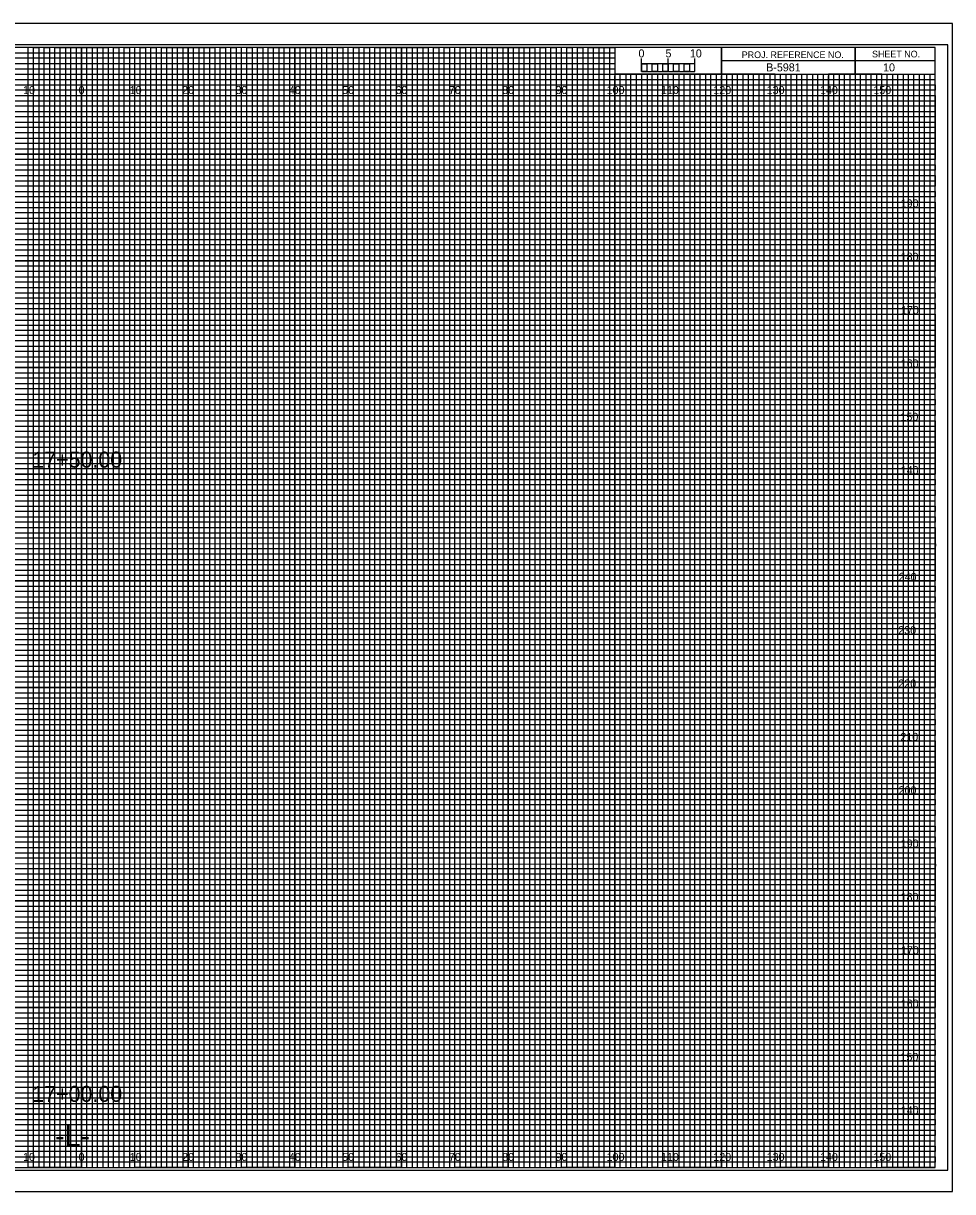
# Model space of a CAD drawing. Extents: x -13 to 323, y -5 to 4174.
# Drawn here: x 149.1 to 323.3, y 875.5 to 1094.5 of the extents above; entities that cross this region are included whole.
import ezdxf

# ---------------------------------------------------------------- set-up
doc = ezdxf.new("R2010")
doc.units = 0
for name, color, linetype in [('Exist Cross Section Cell', 7, 'Continuous'), ('Exist XS Center Line Elevation Label', 7, 'Continuous'), ('Exist XS Ground Line', 7, 'Continuous'), ('Prop CMT Concrete Structures', 7, 'Continuous'), ('Prop CMT Guardrail Graphics', 7, 'Continuous'), ('Prop CMT Pvmt Course 1', 7, 'Continuous'), ('Prop CMT Pvmt Course 2', 7, 'Continuous'), ('Prop CMT Pvmt Course 3', 7, 'Continuous'), ('Prop CMT Pvmt Surface', 7, 'Continuous'), ('Prop CMT Shld Paved Course 1', 7, 'Continuous'), ('Prop CMT Shld Paved Course 2', 7, 'Continuous'), ('Prop CMT Shld Paved Course 3', 7, 'Continuous'), ('Prop CMT Subgrade Earthwork', 7, 'Continuous'), ('Prop XS Ditch Standard Text', 7, 'Continuous'), ('Prop XS SE Text', 7, 'Continuous'), ('Prop XS Side Slope Text', 7, 'Continuous'), ('Scratch_Level_0', 7, 'Continuous')]:
    doc.layers.add(name, color=color, linetype=linetype)

msp = doc.modelspace()

# ---------------------------------------------------------------- linework, layer by layer
at = {"layer": 'Exist XS Center Line Elevation Label'}
for points in [[(145, 880), (155, 880), (155, 1090), (165, 1090), (165, 880), (175, 880), (175, 1090), (185, 1090), (185, 880), (195, 880), (195, 1090), (205, 1090), (205, 880), (215, 880), (215, 1090), (225, 1090), (225, 880), (235, 880), (235, 1090), (245, 1090), (245, 880), (255, 880), (255, 1090), (259.93, 1090), (260, 1090), (260, 1085), (264.99, 1085), (264.99, 880), (275, 880), (275, 1085), (285, 1085), (285, 880), (295, 880), (295, 1085), (305, 1085), (305, 880), (315, 880), (315, 1085)], [(0, 1085), (275, 1085)], [(0, 1065), (320, 1065), (320, 1075), (0, 1075)], [(0, 1045), (320, 1045), (320, 1055), (0, 1055)], [(0, 1025), (320, 1025), (320, 1035), (0, 1035)], [(0, 1005), (320, 1005), (320, 1015), (0, 1015)], [(0, 985), (320, 985), (320, 995), (0, 995)], [(0, 965), (320, 965), (320, 975), (0, 975)], [(0, 945), (320, 945), (320, 955), (0, 955)], [(0, 925), (320, 925), (320, 935), (0, 935)], [(0, 905), (320, 905), (320, 915), (0, 915)], [(0, 885), (320, 885), (320, 895), (0, 895)]]:
    msp.add_lwpolyline(points, dxfattribs=at)
at = {"layer": 'Exist XS Ground Line'}
for p, q in [((150, 1090), (140, 1090)), ((150, 880), (150, 1090)), ((170, 1090), (160, 1090)), ((160, 1090), (160, 880)), ((170, 880), (170, 1090)), ((190, 1090), (180, 1090)), ((180, 1090), (180, 880)), ((190, 880), (190, 1090)), ((210, 1090), (200, 1090)), ((200, 1090), (200, 880)), ((210, 880), (210, 1090)), ((230, 1090), (220, 1090)), ((220, 1090), (220, 880)), ((230, 880), (230, 1090)), ((250, 1090), (240, 1090)), ((240, 1090), (240, 880)), ((250, 880), (250, 1090)), ((260, 1090), (260, 880)), ((270, 880), (270, 1085)), ((290, 1085), (280, 1085)), ((280, 1085), (280, 880)), ((290, 880), (290, 1085)), ((310, 1085), (300, 1085)), ((300, 1085), (300, 880)), ((310, 880), (310, 1085)), ((160, 880), (150, 880)), ((180, 880), (170, 880)), ((200, 880), (190, 880)), ((220, 880), (210, 880)), ((240, 880), (230, 880)), ((260, 880), (250, 880)), ((280, 880), (270, 880)), ((300, 880), (290, 880)), ((320, 880), (310, 880)), ((320, 880), (320, 880))]:
    msp.add_line(p, q, dxfattribs=at)
for points in [[(0, 1080), (320, 1080), (320, 1070), (0, 1070)], [(0, 1060), (320, 1060), (320, 1050), (0, 1050)], [(0, 1040), (320, 1040), (320, 1030), (0, 1030)], [(0, 1020), (320, 1020), (320, 1010), (0, 1010)], [(0, 1000), (320, 1000), (320, 990), (0, 990)], [(0, 980), (320, 980), (320, 970), (0, 970)], [(0, 960), (320, 960), (320, 950), (0, 950)], [(0, 940), (320, 940), (320, 930), (0, 930)], [(0, 920), (320, 920), (320, 910), (0, 910)], [(0, 900), (320, 900), (320, 890), (0, 890)]]:
    msp.add_lwpolyline(points, dxfattribs=at)
at = {"layer": 'Prop CMT Pvmt Course 1'}
for p, q in [((323.3, 1094.5), (-13.4, 1094.5)), ((-13.4, 875.5), (323.3, 875.5))]:
    msp.add_line(p, q, dxfattribs=at)
at = {"layer": 'Prop CMT Pvmt Course 2'}
msp.add_lwpolyline([(-13.4, 875.5), (323.3, 875.5), (323.3, 1094.5), (-13.4, 1094.5)], close=True, dxfattribs=at)
at = {"layer": 'Prop CMT Pvmt Course 3'}
msp.add_lwpolyline([(-10.8, 879.5), (322.4, 879.5), (322.4, 1090.5), (-10.8, 1090.5)], close=True, dxfattribs=at)
at = {"layer": 'Prop CMT Shld Paved Course 1'}
for p, q in [((305, 1090), (305, 1085)), ((305, 1085), (305, 1090)), ((280, 1087.5), (280, 1085)), ((320, 1087.49), (280, 1087.49)), ((280, 1085), (320, 1085))]:
    msp.add_line(p, q, dxfattribs=at)
for points in [[(320, 1090), (0, 1090), (0, 880), (320, 880)], [(280, 1090), (260, 1090), (260, 1085.03), (280, 1085.03)], [(320, 1090), (280, 1090), (280, 1085), (320, 1085)]]:
    msp.add_lwpolyline(points, close=True, dxfattribs=at)
at = {"layer": 'Prop CMT Shld Paved Course 2'}
for p, q in [((267, 1085), (266.01, 1085)), ((266.01, 1085), (266.01, 880)), ((267, 880), (267, 1085)), ((269, 1085), (268, 1085)), ((268, 1085), (268, 880)), ((269, 880), (269, 1085)), ((266.01, 880), (265, 880)), ((268, 880), (267, 880))]:
    msp.add_line(p, q, dxfattribs=at)
for points in [[(150, 880), (151, 880), (151, 1090), (152, 1090), (152, 880)], [(152, 880), (153, 880), (153, 1090), (154, 1090), (154, 880)], [(155, 880), (156, 880), (156, 1090), (157, 1090), (157, 880)], [(157, 880), (158, 880), (158, 1090), (159, 1090), (159, 880)], [(160, 880), (161, 880), (161, 1090), (162, 1090), (162, 880)], [(162, 880), (163, 880), (163, 1090), (164, 1090), (164, 880)], [(165, 880), (166, 880), (166, 1090), (167, 1090), (167, 880)], [(167, 880), (168, 880), (168, 1090), (169, 1090), (169, 880)], [(170, 880), (171, 880), (171, 1090), (172, 1090), (172, 880)], [(172, 880), (173, 880), (173, 1090), (174, 1090), (174, 880)], [(175, 880), (176, 880), (176, 1090), (177, 1090), (177, 880)], [(177, 880), (178, 880), (178, 1090), (179, 1090), (179, 880)], [(180, 880), (181, 880), (181, 1090), (182, 1090), (182, 880)], [(182, 880), (183, 880), (183, 1090), (184, 1090), (184, 880)], [(185, 880), (186, 880), (186, 1090), (187, 1090), (187, 880)], [(187, 880), (188, 880), (188, 1090), (189, 1090), (189, 880)], [(190, 880), (191, 880), (191, 1090), (192, 1090), (192, 880)], [(192, 880), (193, 880), (193, 1090), (194, 1090), (194, 880)], [(195, 880), (196, 880), (196, 1090), (197, 1090), (197, 880)], [(197, 880), (198, 880), (198, 1090), (199, 1090), (199, 880)], [(200, 880), (201, 880), (201, 1090), (202, 1090), (202, 880)], [(202, 880), (203, 880), (203, 1090), (204, 1090), (204, 880)], [(205, 880), (206, 880), (206, 1090), (207, 1090), (207, 880)], [(207, 880), (208, 880), (208, 1090), (209, 1090), (209, 880)], [(210, 880), (211, 880), (211, 1090), (212, 1090), (212, 880)], [(212, 880), (213, 880), (213, 1090), (214, 1090), (214, 880)], [(215, 880), (216, 880), (216, 1090), (217, 1090), (217, 880)], [(217, 880), (218, 880), (218, 1090), (219, 1090), (219, 880)], [(220, 880), (221, 880), (221, 1090), (222, 1090), (222, 880)], [(222, 880), (223, 880), (223, 1090), (224, 1090), (224, 880)], [(225, 880), (226, 880), (226, 1090), (227, 1090), (227, 880)], [(227, 880), (228, 880), (228, 1090), (229, 1090), (229, 880)], [(230, 880), (231, 880), (231, 1090), (232, 1090), (232, 880)], [(232, 880), (233, 880), (233, 1090), (234, 1090), (234, 880)], [(235, 880), (236, 880), (236, 1090), (237, 1090), (237, 880)], [(237, 880), (238, 880), (238, 1090), (239, 1090), (239, 880)], [(240, 880), (241, 880), (241, 1090), (242, 1090), (242, 880)], [(242, 880), (243, 880), (243, 1090), (244, 1090), (244, 880)], [(245, 880), (246, 880), (246, 1090), (247, 1090), (247, 880)], [(247, 880), (248, 880), (248, 1090), (249, 1090), (249, 880)], [(250, 880), (251, 880), (251, 1090), (252, 1090), (252, 880)], [(252, 880), (253, 880), (253, 1090), (254, 1090), (254, 880)], [(255, 880), (256, 880), (256, 1090), (257, 1090), (257, 880)], [(257, 880), (258, 880), (258, 1090), (259, 1090), (259, 880)], [(260, 880), (261, 880), (261, 1085), (262.02, 1085), (262.02, 880)], [(262, 880), (263, 880), (263, 1085), (263.99, 1085), (263.99, 880)], [(270, 880), (270.98, 880), (270.98, 1085), (272, 1085), (272, 880)], [(272, 880), (273, 880), (273, 1085), (274.05, 1085), (274.05, 880)], [(275, 880), (276, 880), (276, 1085), (277, 1085), (277, 880)], [(277, 880), (278, 880), (278, 1085), (279, 1085), (279, 880)], [(280, 880), (281, 880), (281, 1085), (282, 1085), (282, 880)], [(282, 880), (283, 880), (283, 1085), (284, 1085), (284, 880)], [(285, 880), (286, 880), (286, 1085), (287, 1085), (287, 880)], [(287, 880), (288, 880), (288, 1085), (289, 1085), (289, 880)], [(290, 880), (291, 880), (291, 1085), (292, 1085), (292, 880)], [(292, 880), (293, 880), (293, 1085), (294, 1085), (294, 880)], [(295, 880), (296, 880), (296, 1085), (297, 1085), (297, 880)], [(297, 880), (298, 880), (298, 1085), (299, 1085), (299, 880)], [(300, 880), (301, 880), (301, 1085), (302, 1085), (302, 880)], [(302, 880), (303, 880), (303, 1085), (304, 1085), (304, 880)], [(305, 880), (306, 880), (306, 1085), (307, 1085), (307, 880)], [(307, 880), (308, 880), (308, 1085), (309, 1085), (309, 880)], [(310, 880), (311, 880), (311, 1085), (312, 1085), (312, 880)], [(312, 880), (313, 880), (313, 1085), (314, 1085), (314, 880)], [(315, 880), (316, 880), (316, 1085), (317, 1085), (317, 880)], [(317, 880), (318, 880), (318, 1085), (319, 1085), (319, 880)]]:
    msp.add_lwpolyline(points, dxfattribs=at)
at = {"layer": 'Prop CMT Shld Paved Course 3'}
for p, q in [((265, 1085.49), (265, 1087.9)), ((265, 1086.9), (265, 1087.9)), ((270, 1085.49), (270, 1087.9)), ((275, 1085.49), (275, 1087.9)), ((275, 1086.9), (275, 1087.9))]:
    msp.add_line(p, q, dxfattribs=at)
for points in [[(275, 1086.9), (265, 1086.9), (265, 1085.49), (275, 1085.49)], [(265, 1086.9), (266, 1086.9), (266, 1085.49), (265, 1085.49)], [(267, 1086.9), (268, 1086.9), (268, 1085.49), (267, 1085.49)], [(269, 1086.9), (270, 1086.9), (270, 1085.49), (269, 1085.49)], [(271, 1086.9), (272, 1086.9), (272, 1085.49), (271, 1085.49)], [(273, 1086.9), (274, 1086.9), (274, 1085.49), (273, 1085.49)]]:
    msp.add_lwpolyline(points, close=True, dxfattribs=at)
at = {"layer": 'Prop CMT Subgrade Earthwork'}
for p, q in [((150, 880), (150, 1090)), ((160, 880), (160, 1090)), ((170, 880), (170, 1090)), ((180, 880), (180, 1090)), ((190, 880), (190, 1090)), ((200, 880), (200, 1090)), ((210, 880), (210, 1090)), ((220, 880), (220, 1090)), ((230, 880), (230, 1090)), ((240, 880), (240, 1090)), ((250, 880), (250, 1090)), ((260, 880), (260, 1084.69)), ((270, 880), (270, 1084.69)), ((280, 880), (280, 1084.69)), ((290, 880), (290, 1084.69)), ((300, 880), (300, 1084.69)), ((310, 880), (310, 1084.69)), ((0, 1080), (320, 1080)), ((0, 1070), (320, 1070)), ((0, 1060), (320, 1060)), ((0, 1050), (320, 1050)), ((0, 1040), (320, 1040)), ((0, 1030), (320, 1030)), ((0, 1020), (320, 1020)), ((0, 1010), (320, 1010)), ((0, 1000), (320, 1000)), ((0, 990), (320, 990)), ((0, 980), (320, 980)), ((0, 970), (320, 970)), ((0, 960), (320, 960)), ((0, 950), (320, 950)), ((0, 940), (320, 940)), ((0, 930), (320, 930)), ((0, 920), (320, 920)), ((0, 910), (320, 910)), ((0, 900), (320, 900)), ((0, 890), (320, 890))]:
    msp.add_line(p, q, dxfattribs=at)
at = {"layer": 'Scratch_Level_0'}
for p, q in [((0, 1089), (260, 1089)), ((260, 1089), (260, 1087.98)), ((260, 1087.98), (0, 1087.98)), ((0, 1087), (260, 1087)), ((260, 1087), (260, 1085.89)), ((260, 1085.89), (0, 1085.89)), ((0, 1084), (320, 1084))]:
    msp.add_line(p, q, dxfattribs=at)
for points in [[(0, 1083), (270, 1083), (320, 1083), (320, 1082), (0, 1082)], [(0, 1081), (320, 1081), (320, 1079), (0, 1079)], [(0, 1078), (320, 1078), (320, 1077), (0, 1076.98)], [(0, 1076), (320, 1076), (320, 1074), (0, 1074)], [(0, 1073), (320, 1073), (320, 1072), (0, 1072)], [(0, 1071), (320, 1071), (320, 1069), (0, 1069)], [(0, 1068), (320, 1068), (320, 1067), (0, 1067)], [(0, 1066), (320, 1066), (320, 1064), (0, 1064)], [(0, 1063), (320, 1063), (320, 1062), (0, 1062)], [(0, 1061), (320, 1061), (320, 1059), (0, 1059)], [(0, 1058), (320, 1058), (320, 1057), (0, 1057)], [(0, 1056), (320, 1056), (320, 1053.95), (320, 1053), (320, 1052), (0, 1052)], [(0, 1054), (320, 1054), (320, 1053), (0, 1053)], [(0, 1051), (320, 1051), (320, 1049), (0, 1049.03)], [(0, 1049.03), (320, 1049), (320, 1048), (0, 1048)], [(0, 1047), (320, 1047), (320, 1046), (0, 1046)], [(0, 1044), (320, 1044), (320, 1043), (0, 1043)], [(0, 1042), (320, 1042), (320, 1041), (0, 1041)], [(-0.07, 1038.89), (320, 1038.89), (320, 1037.88), (-0.07, 1037.88)], [(0, 1037), (320, 1037), (320, 1036), (0, 1036)], [(0, 1034), (320, 1034), (320, 1033), (0, 1033)], [(0, 1032), (320, 1032), (320, 1031), (0, 1031)], [(0, 1029), (320, 1029), (320, 1028), (0, 1028)], [(0, 1027), (320, 1027), (320, 1026), (0, 1026)], [(0, 1024), (320, 1024), (320, 1023), (0, 1023)], [(0, 1022), (320, 1022), (320, 1021), (0, 1021)], [(0, 1019), (320, 1019), (319.99, 1017.98), (0, 1018)], [(0, 1017), (320, 1017), (320, 1016), (0, 1016)], [(0, 1014), (320, 1014), (320, 1013), (0, 1013)], [(0, 1012), (320, 1012), (320, 1011), (0, 1011)], [(0, 1009), (320, 1009), (320, 1008), (0, 1008)], [(0, 1007), (320, 1007), (320, 1006), (0, 1006)], [(0, 1004), (320, 1004), (320, 1003), (0, 1003)], [(0, 1002), (320, 1002), (320, 1001), (0, 1001)], [(0, 999), (320, 999), (320, 998), (0, 998)], [(0, 996.99), (320.07, 996.91), (320, 996), (0, 996)], [(0, 994), (320, 994), (320, 993), (0, 993)], [(0, 992), (320, 992), (320, 991), (0, 991)], [(0, 989), (320, 989), (320, 988), (0, 988)], [(0, 987), (320, 987), (320, 986), (0, 986)], [(0, 984), (320, 984), (320, 983), (0, 983)], [(0, 982), (320, 982), (320, 981), (0, 981)], [(0, 979), (320, 979), (320, 978), (0, 978)], [(0, 977), (320, 977), (320, 976), (0, 976)], [(0, 974), (320, 974), (320, 973), (0, 973)], [(0, 972), (320, 972), (320, 971), (0, 971)], [(0, 969), (320, 969), (320, 968), (0, 968)], [(0, 967), (320, 967), (320, 966), (0, 966)], [(0, 964), (320, 964), (320, 963), (0, 963)], [(0, 962), (320, 962), (320, 961), (0, 961)], [(0, 959), (320, 959), (319.99, 957.98), (0, 958)], [(0, 957), (320, 957), (320, 956), (0, 956)], [(0, 954), (320, 954), (320, 953), (0, 953)], [(0, 952), (320, 952), (320, 951), (0, 951)], [(0, 949), (320, 949), (320, 948), (0, 948)], [(0, 947), (320, 947), (320, 946), (0, 946)], [(0, 944), (320, 944), (320, 943), (0, 943)], [(0, 942), (320, 942), (320, 941), (0, 941)], [(0, 939), (320, 939), (320, 938), (0, 938)], [(0, 936.99), (320.07, 936.91), (320, 936), (0, 936)], [(0, 934), (320, 934), (320, 933), (0, 933)], [(0, 932), (320, 932), (320, 931), (0, 931)], [(0, 929), (320, 929), (320, 928), (0, 928)], [(0, 927), (320, 927), (320, 926), (0, 926)], [(0, 924), (320, 924), (320, 923), (0, 923)], [(0, 922), (320, 922), (320, 921), (0, 921)], [(0, 919), (320, 919), (320, 918), (0, 918)], [(0, 917), (320, 917), (320, 916), (0, 916)], [(0, 914), (320, 914), (320, 913), (0, 913)], [(0, 912), (320, 912), (320, 911), (0, 911)], [(0, 909), (320, 909), (320, 908), (0, 908)], [(0, 907), (320, 907), (320, 906), (0, 906)], [(0, 904), (320, 904), (320, 903), (0, 903)], [(0, 902), (320, 902), (320, 901), (0, 901)], [(0, 899), (320, 899), (320, 898), (0, 898)], [(0, 897), (320, 897), (320, 896), (0, 896)], [(0, 894), (320, 894), (320, 893), (0, 893)], [(0, 892), (320, 892), (320, 891), (0, 891)], [(0, 889), (320, 889), (320, 888), (0, 888)], [(0, 887), (320, 887), (320, 886), (0, 886)], [(0, 884), (320, 884), (320, 883), (0, 883)], [(0, 882), (320, 882), (320, 881), (0, 881)]]:
    msp.add_lwpolyline(points, dxfattribs=at)

# ---------------------------------------------------------------- texts
at = {"layer": 'Exist Cross Section Cell'}
for s, p in [('10', (149.04, 1081.25)), ('0', (159.45, 1081.25)), ('0', (159.45, 1081.25)), ('10', (169.04, 1081.25)), ('20', (178.86, 1081.25)), ('30', (188.86, 1081.25)), ('40', (198.86, 1081.25)), ('50', (208.86, 1081.25)), ('60', (218.86, 1081.25)), ('70', (228.86, 1081.25)), ('80', (238.86, 1081.25)), ('90', (248.86, 1081.25)), ('100', (258.44, 1081.25)), ('110', (268.62, 1081.25)), ('120', (278.44, 1081.25)), ('130', (288.44, 1081.25)), ('140', (298.44, 1081.25)), ('150', (308.44, 1081.25)), ('10', (149.04, 881.25)), ('0', (159.45, 881.25)), ('0', (159.45, 881.25)), ('10', (169.04, 881.25)), ('20', (178.86, 881.25)), ('30', (188.86, 881.25)), ('40', (198.86, 881.25)), ('50', (208.86, 881.25)), ('60', (218.86, 881.25)), ('70', (228.86, 881.25)), ('80', (238.86, 881.25)), ('90', (248.86, 881.25)), ('100', (258.44, 881.25)), ('110', (268.62, 881.25)), ('120', (278.44, 881.25)), ('130', (288.44, 881.25)), ('140', (298.44, 881.25)), ('150', (308.44, 881.25))]:
    msp.add_text(s, height=1.5, dxfattribs=at).set_placement(p)
at = {"layer": 'Prop CMT Concrete Structures'}
for s, p in [('17+50.00', (150.77, 1011.22)), ('17+00.00', (150.77, 892.33))]:
    msp.add_text(s, height=3, dxfattribs=at).set_placement(p)
at = {"layer": 'Prop CMT Guardrail Graphics'}
for s, p in [('190', (313.57, 1060)), ('180', (313.55, 1050)), ('170', (313.61, 1040)), ('160', (313.57, 1030)), ('150', (313.52, 1020)), ('140', (313.57, 1010)), ('240', (313.19, 990)), ('230', (313.11, 980)), ('220', (313.12, 970)), ('210', (313.5, 960)), ('200', (313.17, 950)), ('190', (313.57, 940)), ('180', (313.55, 930)), ('170', (313.61, 920)), ('160', (313.57, 910)), ('150', (313.52, 900)), ('140', (313.57, 890))]:
    msp.add_text(s, height=1.5, dxfattribs=at).set_placement(p)
at = {"layer": 'Prop CMT Pvmt Surface'}
for s, p in [('5', (269.47, 1088.12)), ('10', (274.04, 1088.12))]:
    msp.add_text(s, height=1.5, dxfattribs=at).set_placement(p)
at = {"layer": 'Prop CMT Shld Paved Course 1'}
for s, p in [('PROJ. REFERENCE NO.', (283.77, 1087.99)), ('SHEET NO.', (308.19, 1088.12))]:
    msp.add_text(s, height=1.25, dxfattribs=at).set_placement(p)
at = {"layer": 'Prop CMT Shld Paved Course 3'}
msp.add_text('0', height=1.5, dxfattribs=at).set_placement((264.41, 1088.12))
at = {"layer": 'Prop XS Ditch Standard Text'}
msp.add_text('-L-', height=4, dxfattribs=at).set_placement((155.06, 884))
at = {"layer": 'Prop XS SE Text'}
msp.add_text(' B-5981', height=1.5, dxfattribs=at).set_placement((287.79, 1085.5))
at = {"layer": 'Prop XS Side Slope Text'}
msp.add_text('10', height=1.5, dxfattribs=at).set_placement((310.26, 1085.5))

doc.saveas('drawing.dxf')
